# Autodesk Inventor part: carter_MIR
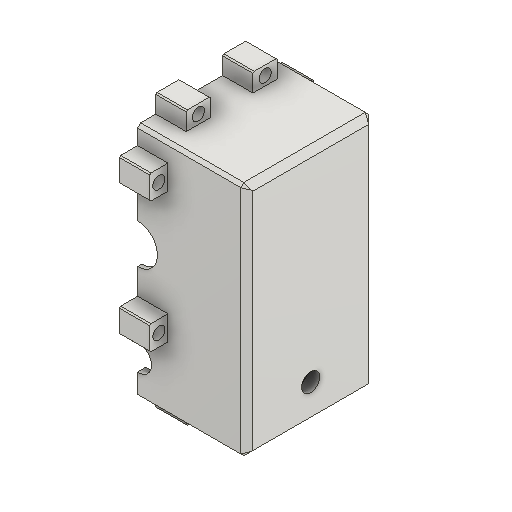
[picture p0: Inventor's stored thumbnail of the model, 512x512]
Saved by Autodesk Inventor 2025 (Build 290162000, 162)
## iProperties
Created: 2026-05
Part Number: carter_MIR
Material: Acciaio
Document SubType Name: Modeling
Designer: Ryzen5700u
Density: 7.85 g/cm^3
Appearance: Acciaio
Author: R5800u
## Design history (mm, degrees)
derived "carter.ipt"
  sketch "Schizzo1"
    geometry: L1 (0, -58)-(-160, -58) reference; L2 (-160, -58)-(-160, 332) reference; L3 (-160, 332)-(0, 332) reference; L4 (0, 332)-(0, -58) reference; C1 r 12 at (0, 0) reference; C2 r 31 at (0, 0) reference; C3 r 45 at (0, 162) reference; A1 r 19.5 centre (0, 162) between (18.547, 168.023) and (18.561, 156.023) reference; 1 further point
  sketch "Schizzo2"
    geometry: L1 (0, 390)-(-35, 390) reference; L2 (-210, 0)-(-210, 390) reference; L3 (0, 390)-(-210, 390) reference; L4 (-210, 390)-(-210, 0) reference; L5 (-210, 0)-(0, 0) reference; L6 (0, 0)-(0, 390) reference; 1 further point
  sketch "Schizzo3"
    geometry: L1 (175, 390)-(35, 390) reference; L2 (175, 390)-(175, 0) reference; L3 (35, 390)-(175, 390) reference; L4 (175, 390)-(175, 370) reference; L5 (175, 370)-(35, 370) reference; L6 (35, 370)-(35, 390) reference; L7 (0, 0)-(35, 0) reference; L8 (35, 0)-(175, 0) reference; L9 (175, 0)-(175, 20) reference; L10 (175, 20)-(35, 20) reference; L11 (35, 20)-(35, 0) reference; 1 further point
  sketch "Schizzo4"
    geometry: L1 (0, 170)-(0, 45) reference; L2 (0, 170)-(180, 170) reference; L3 (180, -220)-(180, 170) reference; L4 (0, -220)-(180, -220) reference; L5 (0, -193)-(0, -220) reference; L6 (0, -45)-(0, -131) reference; L7 (0, 45)-(0, -45) reference; C1 r 32.5 at (0, 0) reference; A1 r 31 centre (0, -162) between (0, -193) and (0, -131) reference; A2 r 45 centre (0, 0) between (0, -45) and (0, 45) reference; 1 further point
  sketch "Schizzo5"
    geometry: L1 (0, 332)-(0, 194.5) reference; L2 (0, 332)-(180, 332) reference; L3 (180, -58)-(180, 332) reference; L4 (0, -58)-(180, -58) reference; L5 (0, -31)-(0, -58) reference; L6 (0, 31)-(0, 129.5) reference; L7 (0, 31)-(0, -31) reference; C1 r 21 at (1.789, 0) reference; A1 r 31 centre (0, 0) between (0, -31) and (0, 31) reference; A2 r 32.5 centre (0, 162) between (0, 129.5) and (0, 194.5) reference; 1 further point
  sketch "Schizzo6"
    geometry: L1 (35, 120)-(30, 125) reference; L2 (35, 120)-(35, -12.5) reference; L3 (35, -12.5)-(28, -12.5) reference; L4 (28, 0)-(28, -12.5) reference; L5 (28, 0)-(0, 0) reference; L6 (0, 0)-(0, 105) reference; L7 (-140, 105)-(0, 105) reference; L8 (-140, 0)-(-140, 105) reference; L9 (-168, 0)-(-140, 0) reference; L10 (-168, 0)-(-168, -12.5) reference; L11 (-175, -12.5)-(-168, -12.5) reference; L12 (-175, 120)-(-175, -12.5) reference; L13 (-170, 125)-(-175, 120) reference; L14 (-170, 125)-(30, 125) reference; L15 (-175, -260)-(-170, -265) reference; L16 (-175, -227.924)-(-175, -260) reference; L17 (-175, -227.924)-(-162, -227.924) reference; L18 (-162, -227.924)-(-162, -238) reference; L19 (-162, -238)-(-140, -238) reference; L20 (-140, -245)-(-140, -238) reference; L21 (0, -245)-(-140, -245) reference; L22 (0, -245)-(0, -238) reference; L23 (22, -238)-(0, -238) reference; L24 (22, -227.924)-(22, -238) reference; L25 (35, -227.924)-(22, -227.924) reference; L26 (35, -260)-(35, -227.924) reference; L27 (30, -265)-(35, -260) reference; L28 (-170, -265)-(30, -265) reference; L29 (-175, -77.5)-(-175, -186.076) reference; L30 (-175, -77.5)-(-168, -77.5) reference; L31 (-168, -77.5)-(-168, -90) reference; L32 (-168, -90)-(-140, -90) reference; L33 (-140, -176)-(-140, -90) reference; L34 (-162, -176)-(-140, -176) reference; L35 (-162, -176)-(-162, -186.076) reference; L36 (-175, -186.076)-(-162, -186.076) reference; L37 (35, -186.076)-(35, -77.5) reference; L38 (35, -186.076)-(22, -186.076) reference; L39 (22, -176)-(22, -186.076) reference; L40 (22, -176)-(0, -176) reference; L41 (0, -176)-(0, -90) reference; L42 (28, -90)-(0, -90) reference; L43 (28, -77.5)-(28, -90) reference; L44 (35, -77.5)-(28, -77.5) reference; L45 (-125, 125)-(-125, -265) reference; L46 (30, 125)-(-170, 125) reference; L47 (-70, 125)-(-70, -265) reference; L48 (-15, 125)-(-15, -265) reference; L49 (-175, 75)-(35, 75) reference; L50 (35, -260)-(35, 120) reference; L51 (-145, 95)-(-205, 95) reference; L52 (-205, 95)-(-205, 55) reference; L53 (-205, 55)-(-145, 55) reference; L54 (-145, 55)-(-145, 95) reference; L55 (-145, 95)-(-205, 55) reference; L56 (-205, 95)-(-145, 55) reference; L57 (-145, -235)-(-105, -235) reference; L58 (-105, -235)-(-105, -295) reference; L59 (-105, -295)-(-145, -295) reference; L60 (-145, -295)-(-145, -235) reference; L61 (-145, -235)-(-105, -295) reference; L62 (-105, -235)-(-145, -295) reference; L63 (-35, -235)-(5, -235) reference; L64 (5, -235)-(5, -295) reference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
  sketch "Schizzo7"
    geometry: L1 (35, 120)-(30, 125) reference; L2 (35, 120)-(35, 95) reference; L3 (35, 95)-(65, 95) reference; L4 (65, 95)-(65, 55) reference; L5 (65, 55)-(35, 55) reference; L6 (35, 55)-(35, -12.5) reference; L7 (35, -12.5)-(28, -12.5) reference; L8 (28, 0)-(28, -12.5) reference; L9 (28, 0)-(0, 0) reference; L10 (0, 0)-(0, 105) reference; L11 (-140, 105)-(0, 105) reference; L12 (-140, 0)-(-140, 105) reference; L13 (-168, 0)-(-140, 0) reference; L14 (-168, 0)-(-168, -12.5) reference; L15 (-175, -12.5)-(-168, -12.5) reference; L16 (-175, 55)-(-175, -12.5) reference; L17 (-175, 55)-(-205, 55) reference; L18 (-205, 55)-(-205, 95) reference; L19 (-205, 95)-(-175, 95) reference; L20 (-175, 120)-(-175, 95) reference; L21 (-170, 125)-(-175, 120) reference; L22 (-170, 125)-(-145, 125) reference; L23 (-145, 125)-(-145, 155) reference; L24 (-145, 155)-(-105, 155) reference; L25 (-105, 155)-(-105, 125) reference; L26 (-105, 125)-(-35, 125) reference; L27 (-35, 125)-(-35, 155) reference; L28 (-35, 155)-(5, 155) reference; L29 (5, 155)-(5, 125) reference; L30 (5, 125)-(30, 125) reference; L31 (35, -186.076)-(35, -160) reference; L32 (35, -186.076)-(22, -186.076) reference; L33 (22, -176)-(22, -186.076) reference; L34 (22, -176)-(0, -176) reference; L35 (0, -176)-(0, -90) reference; L36 (28, -90)-(0, -90) reference; L37 (28, -77.5)-(28, -90) reference; L38 (35, -77.5)-(28, -77.5) reference; L39 (35, -120)-(35, -77.5) reference; L40 (35, -120)-(65, -120) reference; L41 (65, -120)-(65, -160) reference; L42 (65, -160)-(35, -160) reference; L43 (5, -265)-(-35, -265) reference; L44 (-175, -260)-(-170, -265) reference; L45 (-175, -227.924)-(-175, -260) reference; L46 (-175, -227.924)-(-162, -227.924) reference; L47 (-162, -227.924)-(-162, -238) reference; L48 (-162, -238)-(-140, -238) reference; L49 (-140, -245)-(-140, -238) reference; L50 (0, -245)-(-140, -245) reference; L51 (0, -245)-(0, -238) reference; L52 (22, -238)-(0, -238) reference; L53 (22, -227.924)-(22, -238) reference; L54 (35, -227.924)-(22, -227.924) reference; L55 (35, -260)-(35, -227.924) reference; L56 (30, -265)-(35, -260) reference; L57 (5, -265)-(30, -265) reference; L58 (5, -265)-(5, -295) reference; L59 (5, -295)-(-35, -295) reference; L60 (-35, -295)-(-35, -265) reference; L61 (-105, -265)-(-35, -265) reference; L62 (-105, -265)-(-105, -295) reference; L63 (-105, -295)-(-145, -295) reference; L64 (-145, -295)-(-145, -265) reference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; 9 further points
  sketch "Schizzo8"
    geometry: L1 (-160, 30)-(-160, 170) reference; L2 (-160, 100)-(-144, 100) reference; 1 further point
  node "Piano di lavoro1"
  node "Piano di lavoro2"
  node "Piano di lavoro3"
  node "Piano di lavoro4"
sketch "Schizzo9"
  geometry: L1 (80, 65)-(0, 65) reference; L2 (80, 65)-(80, 25) reference; L3 (0, 25)-(80, 25) reference; L4 (0, 0)-(0, 25) reference; L5 (0, 0)-(150, 0) reference; L6 (180, 50)-(180, 150) reference; L7 (150, 200)-(0, 200) reference; L8 (0, 175)-(0, 200) reference; L9 (80, 175)-(0, 175) reference; L10 (80, 175)-(80, 135) reference; L11 (0, 135)-(80, 135) reference; L12 (0, 65)-(0, 135) reference; L13 (150, 50)-(150, 0) reference; L14 (180, 50)-(150, 50) reference; L15 (150, 150)-(180, 150) reference; L16 (150, 200)-(150, 150) reference; C1 r 14.917 at (144, 100) reference; 1 further point
extrude "Estrusione1" join sketch "Schizzo9" stored distance "d1" = 10; taper "d2" = 0 deg
sketch "Schizzo10"
  geometry: L1 (5, 385)-(0, 380) reference; L2 (0, 0)-(0, 380) reference; L3 (0, 0)-(5, -5) reference; L4 (155, -5)-(55, -5) reference; L5 (205, -5)-(210, 0) reference; L6 (210, 380)-(210, 0) reference; L7 (210, 380)-(205, 385) reference; L8 (55, 385)-(155, 385) reference; L9 (5, -50)-(5, -5) reference; L10 (50, -55)-(10, -55) reference; L11 (55, -5)-(55, -50) reference; L12 (155, -50)-(155, -5) reference; L13 (200, -55)-(160, -55) reference; L14 (205, -5)-(205, -50) reference; L15 (205, 430)-(205, 385) reference; L16 (160, 435)-(200, 435) reference; L17 (155, 385)-(155, 430) reference; L18 (55, 430)-(55, 385) reference; L19 (10, 435)-(50, 435) reference; L20 (5, 385)-(5, 430) reference; L21 (205, 430)-(200, 435) reference; L22 (160, 435)-(155, 430) reference; L23 (55, 430)-(50, 435) reference; L24 (10, 435)-(5, 430) reference; L25 (5, -50)-(10, -55) reference; L26 (50, -55)-(55, -50) reference; L27 (155, -50)-(160, -55) reference; L28 (200, -55)-(205, -50) reference; L29 (5, -5)-(205, -5); L30 (5, 385)-(205, 385); C1 r 270.277 at (103.909, 191.96); 6 further points
  constraints: 4 end point, 1 centre point, 1 horizontal, 1 parallel, 1 point on line
extrude "Estrusione2" cut sketch "Schizzo10" distance "d3" = 130; taper "d4" = 0 deg
sketch "Schizzo11"
  geometry: C1 r 5.053 at (225, 335) reference; C2 r 5.053 at (225, 120) reference; C3 r 5.053 at (160, 400) reference; C4 r 5.053 at (50, 400) reference; C5 r 5.053 at (-15, 335) reference; C6 r 5.053 at (-15, 120) reference; C7 r 5.053 at (50, -20) reference; C8 r 5.053 at (160, -20) reference; 1 further point
hole "Foro1" sketch "Schizzo11" at (-15, 335), (-15, 120), (50, -20), (160, -20), (225, 120), (225, 335), (160, 400), (50, 400) diameter "d5" = 10.106; stored, may be unused: countersink angle "d9" = 90 deg, drill point angle "d11" = 118 deg; dims "d6" = 24, "d7" = 20, "d8" = 15, "d10" = 8
chamfer "Smusso1" distance "d12" = 10; stored, may be unused: second distance "d13" = 2, angle "d14" = 45 deg
sketch "Schizzo12"
  geometry: L1 (-60, -10)-(-130, -10) reference; L2 (-95, -10)-(-95, 50); 1 further point
  constraints: 2 end point, 1 midpoint, 1 vertical
  dimensions: "d15" = 60 distance of L2.start L2.end
hole "Foro2" sketch "Schizzo12" at (-95, 50) diameter "d16" = 29.83494; stored, may be unused: countersink angle "d20" = 90 deg, drill point angle "d22" = 118 deg; dims "d17" = 64, "d18" = 20, "d19" = 15, "d21" = 8
feature "Solido1::carter.ipt" dims "d0" = 10
tag "Lavorazione contrassegno1"
node "Linea chiusa proiettata1"
node "Linea chiusa proiettata2"
node "Solido1"
